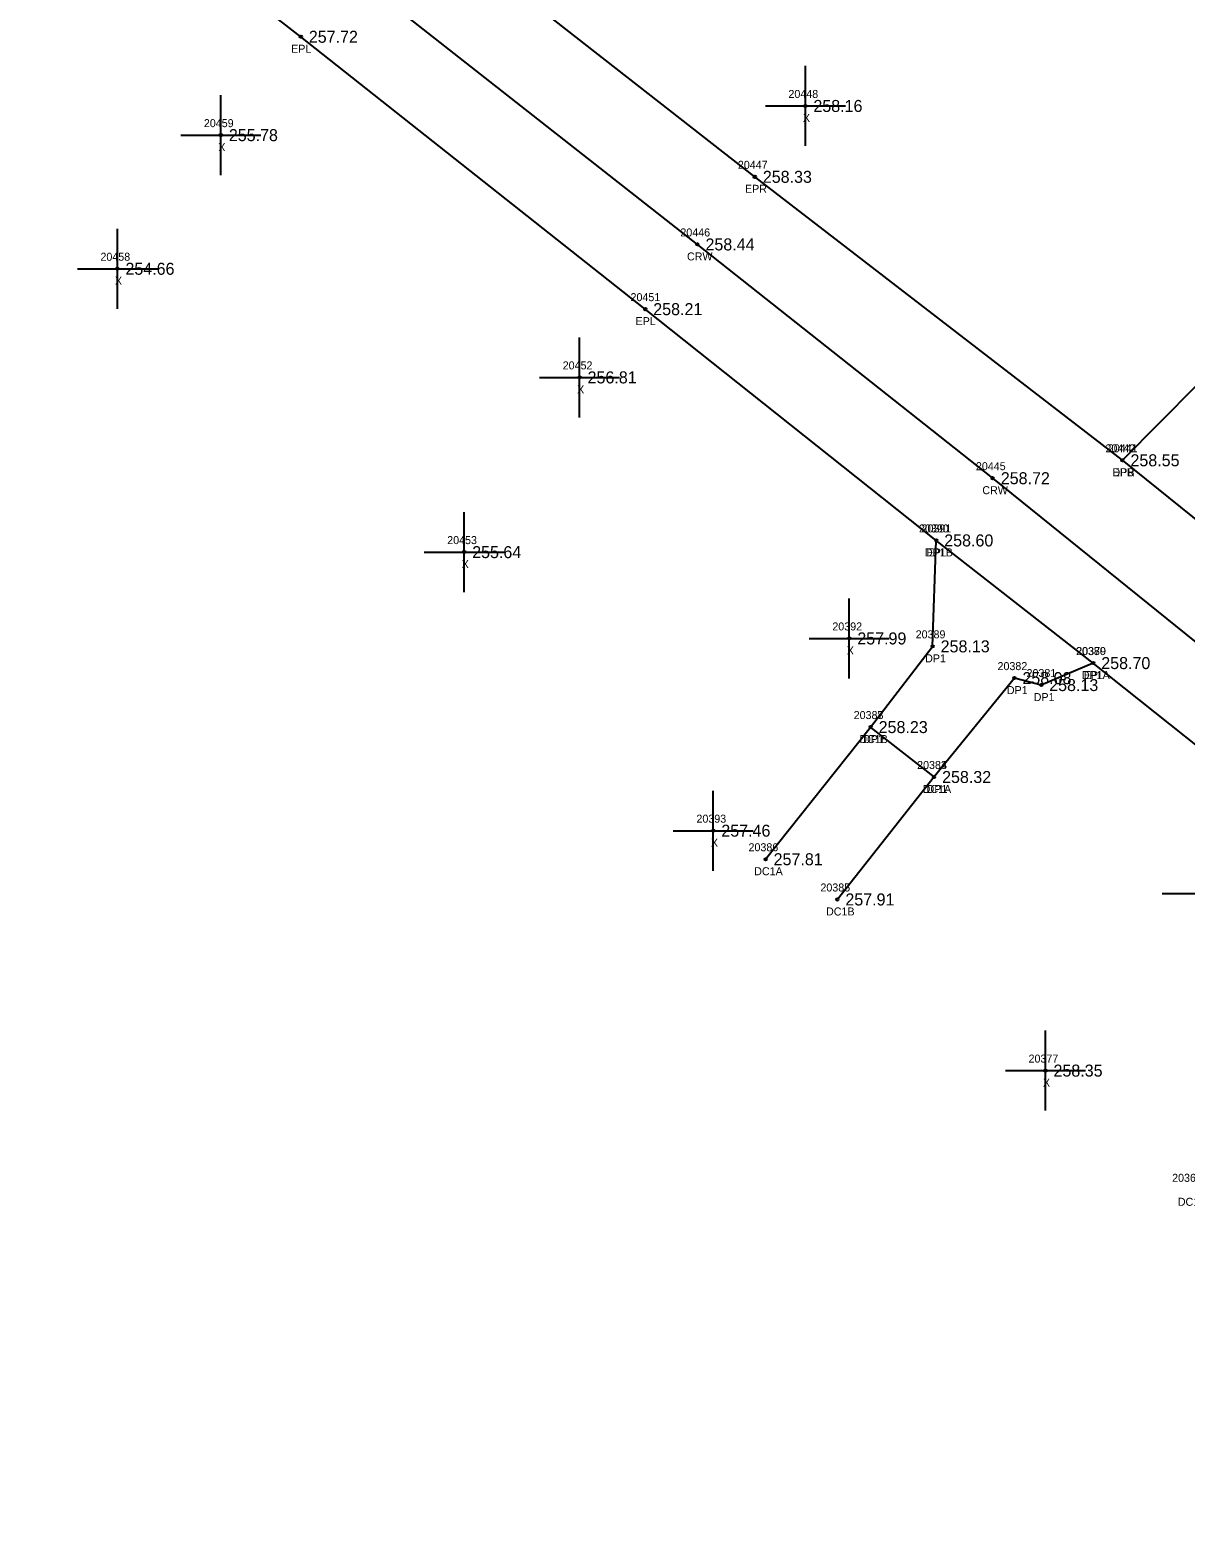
# Model space of a CAD drawing. Extents: x 1961330 to 1962287, y 800294 to 801079.
# Drawn here: x 1961504.5 to 1961649, y 800707 to 800892.8 of the extents above; entities that cross this region are included whole.
import ezdxf

# ---------------------------------------------------------------- set-up
doc = ezdxf.new("R2010")
doc.units = 0
for name, color, linetype in [('RD_DTM_BkLn1', 7, 'Continuous'), ('RD_EX_Conc', 7, 'Continuous'), ('RD_EX_Conc_txCode', 7, 'Continuous'), ('RD_EX_Driveway', 7, 'Continuous'), ('RD_EX_Driveway_txCode', 7, 'Continuous'), ('RD_EX_Misc', 7, 'Continuous'), ('RD_EX_Misc_txCode', 7, 'Continuous'), ('RD_EX_Road', 7, 'Continuous'), ('RD_EX_Road_txCode', 7, 'Continuous'), ('RD_EX_TX_Conc_ELEV', 7, 'Continuous'), ('RD_EX_TX_Driveway_ELEV', 7, 'Continuous'), ('RD_EX_TX_Misc_ELEV', 7, 'Continuous'), ('RD_EX_TX_Road_ELEV', 7, 'Continuous'), ('RD_HC_Survey_ELEV', 7, 'Continuous'), ('RD_HC_Survey_txCode', 7, 'Continuous'), ('RD_SMD_Locator', 7, 'Continuous')]:
    doc.layers.add(name, color=color, linetype=linetype)

msp = doc.modelspace()

# ---------------------------------------------------------------- linework, layer by layer
at = {"layer": 'RD_DTM_BkLn1'}
msp.add_lwpolyline([(1962257.08, 800334.72), (1962203.79, 800372.43), (1962164.31, 800399.58), (1962126.58, 800429.85), (1962084.5, 800463.37), (1962045.12, 800502.48), (1962010.49, 800530.36), (1961971.27, 800562.01), (1961931.18, 800594.14), (1961890.91, 800625.98), (1961844.41, 800662.62), (1961808.07, 800691.13), (1961729.11, 800753.37), (1961696.19, 800780.32), (1961667.25, 800802.66), (1961624.93, 800836.78), (1961588.01, 800866), (1961545.37, 800899.49), (1961472.25, 800957.29), (1961437.91, 800983.99), (1961399.03, 801013.16), (1961365.01, 801035.89)], dxfattribs=at)
at = {"layer": 'RD_EX_Conc'}
for p, q in [((1961596.53, 800789.15), (1961609.66, 800805.67)), ((1961617.59, 800799.43), (1961605.5, 800784.12))]:
    msp.add_line(p, q, dxfattribs=at)
at = {"layer": 'RD_EX_Driveway'}
for points in [[(1961651.45, 800830.73), (1961661.81, 800847.2), (1961655.04, 800853.04), (1961641.14, 800839.02)], [(1961637.49, 800813.67), (1961630.98, 800810.92), (1961627.63, 800811.79), (1961617.59, 800799.43), (1961609.66, 800805.67), (1961617.41, 800815.76), (1961617.86, 800829)]]:
    msp.add_lwpolyline(points, dxfattribs=at)
at = {"layer": 'RD_EX_Misc'}
for p, q in [((1961601.5, 800878.31), (1961601.5, 800888.31)), ((1961528.42, 800874.66), (1961528.42, 800884.66)), ((1961596.5, 800883.31), (1961606.5, 800883.31)), ((1961523.42, 800879.66), (1961533.42, 800879.66)), ((1961515.49, 800857.96), (1961515.49, 800867.96)), ((1961510.49, 800862.96), (1961520.49, 800862.96)), ((1961573.27, 800844.38), (1961573.27, 800854.38)), ((1961568.27, 800849.38), (1961578.27, 800849.38)), ((1961558.84, 800822.54), (1961558.84, 800832.54)), ((1961553.84, 800827.54), (1961563.84, 800827.54)), ((1961606.99, 800811.75), (1961606.99, 800821.75)), ((1961601.99, 800816.75), (1961611.99, 800816.75)), ((1961589.99, 800787.72), (1961589.99, 800797.72)), ((1961584.99, 800792.72), (1961594.99, 800792.72)), ((1961646.11, 800784.87), (1961656.11, 800784.87)), ((1961631.52, 800757.73), (1961631.52, 800767.73)), ((1961626.52, 800762.73), (1961636.52, 800762.73))]:
    msp.add_line(p, q, dxfattribs=at)
at = {"layer": 'RD_EX_Road'}
for points in [[(1961651.45, 800830.73), (1961641.14, 800839.02), (1961595.18, 800874.45), (1961552.9, 800907.54), (1961510.92, 800940.49), (1961504.01, 800946.58), (1961476.53, 800968.16), (1961444.88, 800992.72), (1961406.41, 801021.23), (1961370.69, 801045.26)], [(1961660.52, 800795.31), (1961637.49, 800813.67), (1961617.86, 800829), (1961581.48, 800857.91), (1961538.42, 800891.96), (1961505, 800917.96), (1961467.33, 800947.97), (1961432.02, 800975.33), (1961392.71, 801004.33), (1961360.06, 801026.78)]]:
    msp.add_lwpolyline(points, dxfattribs=at)
at = {"layer": 'RD_SMD_Locator'}
for centre in [(1961538.42, 800891.96), (1961601.5, 800883.31), (1961528.42, 800879.66), (1961595.18, 800874.45), (1961588.01, 800866), (1961515.49, 800862.96), (1961581.48, 800857.91), (1961573.27, 800849.38), (1961641.14, 800839.02), (1961641.14, 800839.02), (1961624.93, 800836.78), (1961617.86, 800829), (1961617.86, 800829), (1961558.84, 800827.54), (1961606.99, 800816.75), (1961617.41, 800815.76), (1961637.49, 800813.67), (1961637.49, 800813.67), (1961627.63, 800811.79), (1961630.98, 800810.92), (1961609.66, 800805.67), (1961609.66, 800805.67), (1961617.59, 800799.43), (1961617.59, 800799.43), (1961589.99, 800792.72), (1961596.53, 800789.15), (1961605.5, 800784.12), (1961631.52, 800762.73)]:
    msp.add_circle(centre, 0.15, dxfattribs=at)

# ---------------------------------------------------------------- texts
at = {"layer": 'RD_EX_Conc_txCode'}
for s, p in [('20387', (1961607.54, 800806.67)), ('DC1B', (1961608.24, 800803.67)), ('20384', (1961615.47, 800800.43)), ('DC1A', (1961616.16, 800797.43)), ('20386', (1961594.39, 800790.15)), ('DC1A', (1961595.1, 800787.15)), ('20385', (1961603.38, 800785.12)), ('DC1B', (1961604.08, 800782.12)), ('20368', (1961647.35, 800748.83)), ('DC1A', (1961648.06, 800745.83))]:
    msp.add_text(s, height=1, dxfattribs=at).set_placement(p)
at = {"layer": 'RD_EX_Driveway_txCode'}
for s, p in [('20442', (1961639.02, 800840.02)), ('DPB', (1961639.89, 800837.02)), ('20390', (1961615.7, 800830)), ('DP1B', (1961616.44, 800827)), ('20389', (1961615.29, 800816.76)), ('DP1', (1961616.47, 800813.76)), ('20380', (1961635.33, 800814.67)), ('20382', (1961625.52, 800812.79)), ('20381', (1961629.15, 800811.92)), ('DP1A', (1961636.06, 800811.67)), ('DP1', (1961626.69, 800809.79)), ('DP1', (1961630.04, 800808.92)), ('20388', (1961607.54, 800806.67)), ('DP1', (1961608.72, 800803.67)), ('20383', (1961615.47, 800800.43)), ('DP1', (1961616.65, 800797.43))]:
    msp.add_text(s, height=1, dxfattribs=at).set_placement(p)
at = {"layer": 'RD_EX_Misc_txCode'}
for s, p in [('20448', (1961599.38, 800884.31)), ('20459', (1961526.3, 800880.66)), ('X', (1961601.19, 800881.31)), ('X', (1961528.1, 800877.66)), ('20458', (1961513.37, 800863.96)), ('X', (1961515.18, 800860.96)), ('20452', (1961571.16, 800850.38)), ('X', (1961572.96, 800847.38)), ('20453', (1961556.72, 800828.54)), ('X', (1961558.53, 800825.54)), ('20392', (1961604.87, 800817.75)), ('X', (1961606.67, 800814.75)), ('20393', (1961587.88, 800793.72)), ('X', (1961589.68, 800790.72)), ('20377', (1961629.4, 800763.73)), ('X', (1961631.2, 800760.73))]:
    msp.add_text(s, height=1, dxfattribs=at).set_placement(p)
at = {"layer": 'RD_EX_Road_txCode'}
for s, p in [('EPL', (1961537.21, 800889.96)), ('20447', (1961593.06, 800875.45)), ('EPR', (1961593.95, 800872.45)), ('20451', (1961579.64, 800858.91)), ('EPL', (1961580.27, 800855.91)), ('20441', (1961639.31, 800840.02)), ('EPR', (1961639.91, 800837.02)), ('20391', (1961616.02, 800830)), ('EPL', (1961616.65, 800827)), ('20379', (1961635.37, 800814.67)), ('EPL', (1961636.29, 800811.67))]:
    msp.add_text(s, height=1, dxfattribs=at).set_placement(p)
at = {"layer": 'RD_EX_TX_Conc_ELEV'}
for s, p in [('258.23', (1961610.66, 800804.92)), ('258.32', (1961618.59, 800798.68)), ('257.81', (1961597.53, 800788.4)), ('257.91', (1961606.5, 800783.37))]:
    msp.add_text(s, height=1.5, dxfattribs=at).set_placement(p)
at = {"layer": 'RD_EX_TX_Driveway_ELEV'}
for s, p in [('258.55', (1961642.14, 800838.27)), ('258.60', (1961618.86, 800828.25)), ('258.13', (1961618.41, 800815.01)), ('258.70', (1961638.49, 800812.92)), ('258.08', (1961628.63, 800811.04)), ('258.13', (1961631.98, 800810.17)), ('258.23', (1961610.66, 800804.92)), ('258.32', (1961618.59, 800798.68))]:
    msp.add_text(s, height=1.5, dxfattribs=at).set_placement(p)
at = {"layer": 'RD_EX_TX_Misc_ELEV'}
for s, p in [('258.16', (1961602.5, 800882.56)), ('255.78', (1961529.42, 800878.91)), ('254.66', (1961516.49, 800862.21)), ('256.81', (1961574.27, 800848.63)), ('255.64', (1961559.84, 800826.79)), ('257.99', (1961607.99, 800816)), ('257.46', (1961590.99, 800791.97)), ('258.35', (1961632.52, 800761.98))]:
    msp.add_text(s, height=1.5, dxfattribs=at).set_placement(p)
at = {"layer": 'RD_EX_TX_Road_ELEV'}
for s, p in [('257.72', (1961539.42, 800891.21)), ('258.33', (1961596.18, 800873.7)), ('258.21', (1961582.48, 800857.16)), ('258.55', (1961642.14, 800838.27)), ('258.60', (1961618.86, 800828.25)), ('258.70', (1961638.49, 800812.92))]:
    msp.add_text(s, height=1.5, dxfattribs=at).set_placement(p)
at = {"layer": 'RD_HC_Survey_ELEV'}
for s, p in [('258.44', (1961589.01, 800865.25)), ('258.72', (1961625.93, 800836.03))]:
    msp.add_text(s, height=1.5, dxfattribs=at).set_placement(p)
at = {"layer": 'RD_HC_Survey_txCode'}
for s, p in [('20446', (1961585.87, 800867)), ('CRW', (1961586.7, 800864)), ('20445', (1961622.82, 800837.78)), ('CRW', (1961623.62, 800834.78))]:
    msp.add_text(s, height=1, dxfattribs=at).set_placement(p)

doc.saveas('drawing.dxf')
